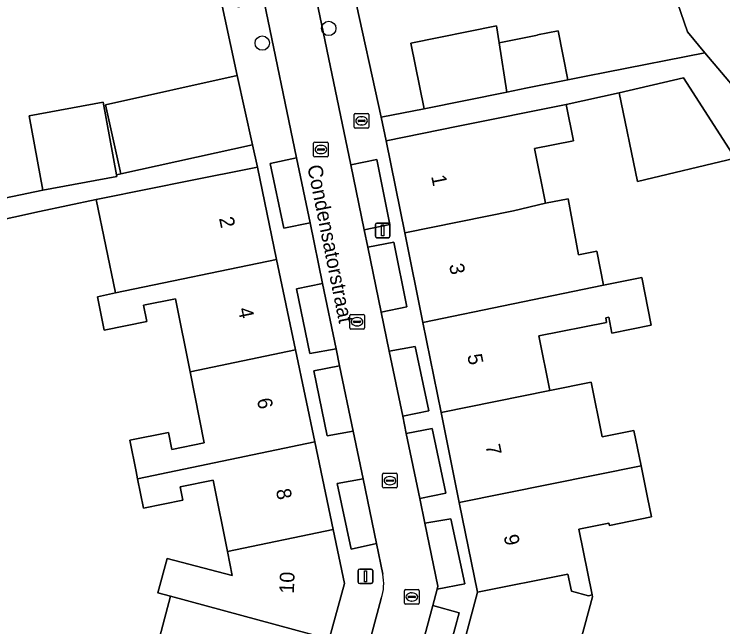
# Model space of a CAD drawing. Extents: x 162989 to 165008, y 383432 to 384338.
# Drawn here: x 163654.72 to 163703.1, y 383947.94 to 383989.79 of the extents above; entities that cross this region are included whole.
import ezdxf

# ---------------------------------------------------------------- set-up
doc = ezdxf.new("R2010")
doc.units = 0
for name, color, linetype in [('IMGEO_Boom', 7, 'Continuous'), ('IMGEO_Brandkraan', 7, 'Continuous'), ('IMGEO_Erf', 7, 'Continuous'), ('IMGEO_Kolk', 7, 'Continuous'), ('IMGEO_Lichtmast', 7, 'Continuous'), ('IMGEO_Openbare_ruimte_label', 7, 'Continuous'), ('IMGEO_Pand', 7, 'Continuous'), ('IMGEO_Pand_nummerreeks', 7, 'Continuous'), ('IMGEO_Parkeervlak_open', 7, 'Continuous'), ('IMGEO_Rijbaan_lokaal_open', 7, 'Continuous'), ('IMGEO_Rioolput', 7, 'Continuous'), ('IMGEO_Terreindeel_gesloten', 7, 'Continuous'), ('IMGEO_Voetpad_open', 7, 'Continuous')]:
    doc.layers.add(name, color=color, linetype=linetype)

msp = doc.modelspace()

# ---------------------------------------------------------------- linework, layer by layer
at = {"layer": 'IMGEO_Boom'}
for centre in [(163676.194, 383988.817), (163671.653, 383987.815)]:
    msp.add_circle(centre, 0.489, dxfattribs=at)
at = {"layer": 'IMGEO_Brandkraan'}
for p, q in [((163677.934, 383982.078), (163677.934, 383982.93)), ((163678.009, 383983.004), (163678.861, 383983.004)), ((163678.935, 383982.93), (163678.935, 383982.078)), ((163678.193, 383982.498), (163678.193, 383982.51)), ((163678.631, 383982.461), (163678.233, 383982.461)), ((163678.236, 383982.547), (163678.634, 383982.547)), ((163678.422, 383982.784), (163678.447, 383982.784)), ((163678.677, 383982.51), (163678.677, 383982.498)), ((163678.861, 383982.004), (163678.009, 383982.004)), ((163678.445, 383982.224), (163678.42, 383982.224))]:
    msp.add_line(p, q, dxfattribs=at)
for points in [[(163677.934, 383982.078), (163677.934, 383982.93)], [(163678.009, 383983.004), (163678.861, 383983.004)], [(163678.935, 383982.93), (163678.935, 383982.078)], [(163678.861, 383982.004), (163678.009, 383982.004)]]:
    msp.add_lwpolyline(points, dxfattribs=at)
for centre, radius, start, end in [((163678.011, 383982.928), 0.0765, 91.552, 178.448), ((163678.011, 383982.928), 0.0765, 91.552, 178.448), ((163678.859, 383982.928), 0.0765, 1.552, 88.448), ((163678.859, 383982.928), 0.0765, 1.552, 88.448), ((163678.233, 383982.507), 0.0403, 85.8775, 175.7526), ((163678.23, 383982.497), 0.0366, 178.938, 274.7102), ((163678.634, 383982.504), 0.043, 264.8664, 352.4533), ((163678.638, 383982.509), 0.0386, 1.7309, 96.639), ((163678.011, 383982.08), 0.0765, 181.552, 268.448), ((163678.011, 383982.08), 0.0765, 181.552, 268.448), ((163678.859, 383982.08), 0.0765, 271.552, 358.448), ((163678.859, 383982.08), 0.0765, 271.552, 358.448)]:
    msp.add_arc(centre, radius, start, end, dxfattribs=at)
for centre, major_axis, ratio, start_param, end_param in [((163678.421, 383982.504), (-0.387, 0.002), 0.722429, 4.712389, 7.853982), ((163678.446, 383982.504), (-0.39, 0.002), 0.717154, 1.570796, 4.712389)]:
    msp.add_ellipse(centre, major_axis=major_axis, ratio=ratio, start_param=start_param, end_param=end_param, dxfattribs=at)
at = {"layer": 'IMGEO_Erf'}
for points in [[(163649.338, 383976.243), (163656.674, 383977.764), (163655.732, 383982.848), (163660.79, 383983.785), (163661.71, 383978.82), (163662.003, 383978.874), (163660.958, 383983.61), (163669.94, 383985.593), (163666.955, 383999.493), (163659.023, 383997.851), (163659.53, 383995.403), (163660.627, 383995.63), (163661.134, 383993.182), (163660.787, 383993.11), (163661.265, 383990.887), (163659.452, 383990.497), (163658.97, 383992.734), (163658.895, 383993.098), (163656.322, 383992.565), (163655.913, 383994.538), (163652.306, 383993.79)], [(163664.02, 383944.869), (163665.382, 383950.025), (163664.53, 383950.25), (163665.153, 383952.612), (163669.603, 383951.438), (163669.273, 383953.081), (163668.295, 383957.948), (163666.041, 383957.495), (163666.225, 383956.579), (163663.54, 383956.04), (163663.136, 383958.052), (163663.037, 383958.543), (163662.605, 383960.691), (163665.243, 383961.221), (163665.477, 383960.058), (163667.698, 383960.504), (163666.724, 383965.353), (163665.72, 383970.349), (163663.544, 383969.912), (163663.769, 383968.792), (163660.865, 383968.209), (163660.408, 383970.486), (163661.643, 383970.744), (163660.309, 383977.13), (163656.443, 383976.322), (163631.374, 383970.769)]]:
    msp.add_lwpolyline(points, dxfattribs=at)
at = {"layer": 'IMGEO_Kolk'}
for p, q in [((163675.235, 383981.046), (163676.087, 383981.046)), ((163675.16, 383980.12), (163675.16, 383980.972)), ((163675.419, 383980.54), (163675.419, 383980.552)), ((163675.857, 383980.503), (163675.459, 383980.503)), ((163675.462, 383980.589), (163675.86, 383980.589)), ((163675.648, 383980.826), (163675.673, 383980.826)), ((163675.903, 383980.552), (163675.903, 383980.54)), ((163676.161, 383980.972), (163676.161, 383980.12)), ((163676.087, 383980.046), (163675.235, 383980.046)), ((163675.671, 383980.266), (163675.646, 383980.266)), ((163677.627, 383968.354), (163677.627, 383969.206)), ((163677.702, 383969.28), (163678.554, 383969.28)), ((163678.115, 383969.06), (163678.14, 383969.06)), ((163678.628, 383969.206), (163678.628, 383968.354)), ((163677.886, 383968.774), (163677.886, 383968.786)), ((163678.324, 383968.737), (163677.926, 383968.737)), ((163677.929, 383968.823), (163678.327, 383968.823)), ((163678.138, 383968.5), (163678.113, 383968.5)), ((163678.37, 383968.786), (163678.37, 383968.774)), ((163678.554, 383968.28), (163677.702, 383968.28)), ((163679.873, 383957.498), (163679.873, 383958.35)), ((163679.948, 383958.424), (163680.8, 383958.424)), ((163680.874, 383958.35), (163680.874, 383957.498)), ((163680.132, 383957.918), (163680.132, 383957.93)), ((163680.57, 383957.881), (163680.172, 383957.881)), ((163680.175, 383957.967), (163680.573, 383957.967)), ((163680.361, 383958.204), (163680.386, 383958.204)), ((163680.616, 383957.93), (163680.616, 383957.918)), ((163680.8, 383957.424), (163679.948, 383957.424)), ((163680.384, 383957.644), (163680.359, 383957.644))]:
    msp.add_line(p, q, dxfattribs=at)
for points in [[(163675.235, 383981.046), (163676.087, 383981.046)], [(163675.16, 383980.12), (163675.16, 383980.972)], [(163676.161, 383980.972), (163676.161, 383980.12)], [(163676.087, 383980.046), (163675.235, 383980.046)], [(163677.627, 383968.354), (163677.627, 383969.206)], [(163677.702, 383969.28), (163678.554, 383969.28)], [(163678.628, 383969.206), (163678.628, 383968.354)], [(163678.554, 383968.28), (163677.702, 383968.28)], [(163679.873, 383957.498), (163679.873, 383958.35)], [(163679.948, 383958.424), (163680.8, 383958.424)], [(163680.874, 383958.35), (163680.874, 383957.498)], [(163680.8, 383957.424), (163679.948, 383957.424)]]:
    msp.add_lwpolyline(points, dxfattribs=at)
for centre, radius, start, end in [((163675.237, 383980.97), 0.0765, 91.552, 178.448), ((163675.237, 383980.97), 0.0765, 91.552, 178.448), ((163676.085, 383980.97), 0.0765, 1.552, 88.448), ((163676.085, 383980.97), 0.0765, 1.552, 88.448), ((163675.459, 383980.549), 0.0403, 85.8775, 175.7526), ((163675.456, 383980.539), 0.0366, 178.938, 274.7102), ((163675.86, 383980.546), 0.043, 264.8664, 352.4533), ((163675.864, 383980.551), 0.0386, 1.7309, 96.639), ((163675.237, 383980.122), 0.0765, 181.552, 268.448), ((163675.237, 383980.122), 0.0765, 181.552, 268.448), ((163676.085, 383980.122), 0.0765, 271.552, 358.448), ((163676.085, 383980.122), 0.0765, 271.552, 358.448), ((163677.704, 383969.204), 0.0765, 91.552, 178.448), ((163677.704, 383969.204), 0.0765, 91.552, 178.448), ((163678.552, 383969.204), 0.0765, 1.552, 88.448), ((163678.552, 383969.204), 0.0765, 1.552, 88.448), ((163677.926, 383968.783), 0.0403, 85.8775, 175.7526), ((163677.923, 383968.773), 0.0366, 178.938, 274.7102), ((163678.327, 383968.78), 0.043, 264.8664, 352.4533), ((163678.331, 383968.785), 0.0386, 1.7309, 96.639), ((163677.704, 383968.356), 0.0765, 181.552, 268.448), ((163677.704, 383968.356), 0.0765, 181.552, 268.448), ((163678.552, 383968.356), 0.0765, 271.552, 358.448), ((163678.552, 383968.356), 0.0765, 271.552, 358.448), ((163679.95, 383958.348), 0.0765, 91.552, 178.448), ((163679.95, 383958.348), 0.0765, 91.552, 178.448), ((163680.798, 383958.348), 0.0765, 1.552, 88.448), ((163680.798, 383958.348), 0.0765, 1.552, 88.448), ((163680.172, 383957.927), 0.0403, 85.8775, 175.7526), ((163680.169, 383957.917), 0.0366, 178.938, 274.7102), ((163680.573, 383957.924), 0.043, 264.8664, 352.4533), ((163680.577, 383957.929), 0.0386, 1.7309, 96.639), ((163679.95, 383957.5), 0.0765, 181.552, 268.448), ((163679.95, 383957.5), 0.0765, 181.552, 268.448), ((163680.798, 383957.5), 0.0765, 271.552, 358.448), ((163680.798, 383957.5), 0.0765, 271.552, 358.448)]:
    msp.add_arc(centre, radius, start, end, dxfattribs=at)
for centre, major_axis, ratio, start_param, end_param in [((163675.647, 383980.546), (-0.387, 0.002), 0.722429, 4.712389, 7.853982), ((163675.672, 383980.546), (-0.39, 0.002), 0.717154, 1.570796, 4.712389), ((163678.114, 383968.78), (-0.387, 0.002), 0.722429, 4.712389, 7.853982), ((163678.139, 383968.78), (-0.39, 0.002), 0.717154, 1.570796, 4.712389), ((163680.36, 383957.924), (-0.387, 0.002), 0.722429, 4.712389, 7.853982), ((163680.385, 383957.924), (-0.39, 0.002), 0.717154, 1.570796, 4.712389)]:
    msp.add_ellipse(centre, major_axis=major_axis, ratio=ratio, start_param=start_param, end_param=end_param, dxfattribs=at)
at = {"layer": 'IMGEO_Lichtmast'}
for p, q in [((163679.378, 383974.623), (163679.378, 383975.423)), ((163679.378, 383975.423), (163679.378, 383974.623)), ((163679.478, 383975.523), (163680.268, 383975.523)), ((163680.268, 383975.523), (163679.478, 383975.523)), ((163680.368, 383975.423), (163680.368, 383974.623)), ((163680.368, 383974.623), (163680.368, 383975.423)), ((163680.268, 383974.523), (163679.478, 383974.523)), ((163679.478, 383974.523), (163680.268, 383974.523)), ((163678.208, 383950.987), (163678.208, 383951.787)), ((163678.208, 383951.787), (163678.208, 383950.987)), ((163678.308, 383951.887), (163679.098, 383951.887)), ((163679.098, 383951.887), (163678.308, 383951.887)), ((163679.198, 383951.787), (163679.198, 383950.987)), ((163679.198, 383950.987), (163679.198, 383951.787)), ((163679.098, 383950.887), (163678.308, 383950.887)), ((163678.308, 383950.887), (163679.098, 383950.887))]:
    msp.add_line(p, q, dxfattribs=at)
for points in [[(163679.798, 383975.398), (163679.948, 383975.398), (163679.948, 383974.648), (163679.798, 383974.648), (163679.798, 383975.398)], [(163678.628, 383951.762), (163678.778, 383951.762), (163678.778, 383951.012), (163678.628, 383951.012), (163678.628, 383951.762)]]:
    msp.add_lwpolyline(points, dxfattribs=at)
for centre, start, end in [((163679.478, 383975.423), 90, 180), ((163679.478, 383975.423), 90, 180), ((163680.268, 383975.423), 0, 90), ((163680.268, 383975.423), 360, 90), ((163679.478, 383974.623), 180, 270), ((163679.478, 383974.623), 180, 270), ((163680.268, 383974.623), 270, 0), ((163680.268, 383974.623), 270, 0), ((163678.308, 383951.787), 90, 180), ((163678.308, 383951.787), 90, 180), ((163679.098, 383951.787), 0, 90), ((163679.098, 383951.787), 360, 90), ((163678.308, 383950.987), 180, 270), ((163678.308, 383950.987), 180, 270), ((163679.098, 383950.987), 270, 0), ((163679.098, 383950.987), 270, 0)]:
    msp.add_arc(centre, 0.1, start, end, dxfattribs=at)
at = {"layer": 'IMGEO_Pand'}
for points in [[(163703.909, 383997.461), (163701.43, 383997.012), (163699.309, 383996.628), (163698.002, 383996.392), (163700.685, 383988.577), (163701.884, 383987.16), (163725.748, 383958.959), (163732.007, 383964.256)], [(163687.821, 383987.842), (163687.64, 383988.996), (163681.808, 383987.821), (163682.712, 383983.332), (163688.349, 383984.467)], [(163687.821, 383987.842), (163688.349, 383984.467), (163689.65, 383984.729), (163692.528, 383985.309), (163691.855, 383988.652), (163690.459, 383988.371), (163690.442, 383988.369)], [(163669.94, 383985.593), (163660.958, 383983.61), (163662.003, 383978.874), (163670.986, 383980.857)], [(163696.019, 383984.426), (163697.272, 383978.372), (163703.944, 383979.959), (163700.411, 383985.439)], [(163660.79, 383983.785), (163655.732, 383982.848), (163656.674, 383977.764), (163661.732, 383978.702), (163661.71, 383978.82)], [(163681.392, 383974.86), (163688.818, 383976.356), (163690.996, 383976.883), (163690.244, 383980.612), (163692.91, 383981.149), (163692.412, 383983.618), (163685.027, 383982.137), (163680.125, 383981.149)], [(163671.32, 383979.343), (163666.419, 383978.358), (163664.156, 383977.903), (163660.309, 383977.13), (163661.643, 383970.744), (163672.636, 383973.04)], [(163694.494, 383973.612), (163693.255, 383973.362), (163692.532, 383977.174), (163690.996, 383976.883), (163688.818, 383976.356), (163681.392, 383974.86), (163682.629, 383968.718), (163694.965, 383971.271)], [(163672.636, 383973.04), (163661.643, 383970.744), (163660.408, 383970.486), (163660.865, 383968.209), (163663.769, 383968.792), (163663.544, 383969.912), (163665.72, 383970.349), (163666.724, 383965.353), (163673.928, 383966.857)], [(163690.543, 383967.808), (163695.164, 383968.738), (163695.103, 383969.043), (163695.314, 383969.086), (163695.534, 383967.995), (163698.218, 383968.536), (163697.562, 383971.794), (163694.965, 383971.271), (163682.629, 383968.718), (163683.866, 383962.577), (163691.295, 383964.077)], [(163666.724, 383965.353), (163667.698, 383960.504), (163665.477, 383960.058), (163665.243, 383961.221), (163662.605, 383960.691), (163663.037, 383958.543), (163663.136, 383958.052), (163675.239, 383960.58), (163673.928, 383966.857)], [(163697.52, 383958.936), (163697.033, 383961.354), (163694.86, 383960.917), (163694.108, 383964.649), (163691.295, 383964.077), (163683.866, 383962.577), (163685.103, 383956.435)], [(163663.136, 383958.052), (163663.54, 383956.04), (163666.225, 383956.579), (163666.041, 383957.495), (163668.295, 383957.948), (163669.273, 383953.081), (163676.49, 383954.588), (163675.239, 383960.58)], [(163693.271, 383954.603), (163695.326, 383955.017), (163695.357, 383954.864), (163698.224, 383955.442), (163697.957, 383956.769), (163697.52, 383958.936), (163685.103, 383956.435), (163686.34, 383950.294), (163692.525, 383951.539), (163692.761, 383950.365), (163693.934, 383950.051), (163694.173, 383950.124)], [(163676.49, 383954.588), (163669.273, 383953.081), (163669.603, 383951.438), (163665.153, 383952.612), (163664.53, 383950.25), (163665.382, 383950.025), (163676.227, 383947.087), (163677.26, 383950.901)], [(163694.199, 383949.993), (163694.173, 383950.124), (163693.934, 383950.051), (163692.761, 383950.365), (163692.525, 383951.539), (163686.34, 383950.294), (163684.751, 383944.336), (163696.922, 383941.077), (163700.854, 383940.736), (163702.069, 383945.343), (163697.97, 383946.428), (163697.154, 383943.476), (163694.808, 383944.104), (163694.612, 383943.373), (163692.573, 383943.919)], [(163676.227, 383947.087), (163665.382, 383950.025), (163664.02, 383944.869), (163663.682, 383943.589), (163667.222, 383942.653), (163667.294, 383942.927), (163674.567, 383940.957)]]:
    msp.add_lwpolyline(points, close=True, dxfattribs=at)
at = {"layer": 'IMGEO_Parkeervlak_open'}
for points in [[(163673.995, 383979.982), (163672.196, 383979.597), (163673.129, 383975.176), (163674.916, 383975.532)], [(163677.694, 383979.491), (163678.612, 383975.053), (163680.366, 383975.43), (163679.474, 383979.854)], [(163678.855, 383973.878), (163679.775, 383969.429), (163681.526, 383969.806), (163680.633, 383974.215)], [(163675.773, 383971.383), (163673.988, 383971.033), (163674.904, 383966.6), (163676.693, 383966.931)], [(163681.243, 383962.33), (163683.02, 383962.686), (163682.102, 383967.099), (163680.324, 383966.774)], [(163676.938, 383965.761), (163675.169, 383965.423), (163676.086, 383960.979), (163677.855, 383961.311)], [(163681.49, 383961.136), (163682.406, 383956.709), (163684.188, 383957.065), (163683.248, 383961.496)], [(163679.446, 383953.639), (163678.534, 383958.049), (163676.761, 383957.728), (163677.719, 383953.253)], [(163682.756, 383955.016), (163683.646, 383950.713), (163683.589, 383950.502), (163685.479, 383950.868), (163684.531, 383955.321)], [(163683.292, 383949.391), (163682.115, 383945.004), (163683.91, 383944.523), (163685.107, 383948.901)]]:
    msp.add_lwpolyline(points, close=True, dxfattribs=at)
at = {"layer": 'IMGEO_Rijbaan_lokaal_open'}
for points in [[(163682.756, 383955.016), (163682.406, 383956.709), (163681.49, 383961.136), (163681.243, 383962.33), (163680.324, 383966.774), (163679.775, 383969.429), (163678.855, 383973.878), (163678.612, 383975.053), (163677.694, 383979.491), (163675.245, 383991.331), (163674.326, 383995.772), (163673.959, 383997.551), (163673.452, 384000), (163673.037, 384002.004), (163671.293, 384010.439)], [(163667.83, 384009.769), (163669.585, 384001.291), (163669.852, 384000), (163670.508, 383996.831), (163670.871, 383995.074), (163671.79, 383990.634), (163673.995, 383979.982), (163674.916, 383975.532), (163675.773, 383971.383), (163676.693, 383966.931), (163676.938, 383965.761), (163677.855, 383961.311), (163678.534, 383958.049), (163679.446, 383953.639), (163679.88, 383951.543)], [(163679.785, 383949.861), (163678.54, 383945.274), (163677.344, 383940.871), (163677.03, 383939.713), (163675.846, 383935.353), (163675.124, 383932.682), (163673.947, 383928.341), (163672.545, 383923.205), (163678.094, 383921.638), (163678.667, 383923.699), (163676.598, 383924.257), (163677.363, 383927.171), (163678.514, 383931.573), (163678.824, 383932.729), (163680.003, 383937.128), (163680.465, 383938.851), (163681.64, 383943.23), (163682.115, 383945.004), (163683.292, 383949.391), (163683.589, 383950.502), (163683.646, 383950.713), (163682.756, 383955.016)]]:
    msp.add_lwpolyline(points, dxfattribs=at)
msp.add_arc((163676.657, 383950.881), 3.29, 341.9321, 11.6026, dxfattribs=at)
at = {"layer": 'IMGEO_Rioolput'}
for p, q in [((163681.367, 383949.552), (163681.367, 383950.404)), ((163681.442, 383950.478), (163682.294, 383950.478)), ((163681.669, 383950.021), (163682.067, 383950.021)), ((163681.855, 383950.258), (163681.88, 383950.258)), ((163682.368, 383950.404), (163682.368, 383949.552)), ((163681.626, 383949.972), (163681.626, 383949.984)), ((163682.064, 383949.935), (163681.666, 383949.935)), ((163681.878, 383949.698), (163681.853, 383949.698)), ((163682.11, 383949.984), (163682.11, 383949.972)), ((163682.294, 383949.478), (163681.442, 383949.478))]:
    msp.add_line(p, q, dxfattribs=at)
for points in [[(163681.367, 383949.552), (163681.367, 383950.404)], [(163681.442, 383950.478), (163682.294, 383950.478)], [(163682.368, 383950.404), (163682.368, 383949.552)], [(163682.294, 383949.478), (163681.442, 383949.478)]]:
    msp.add_lwpolyline(points, dxfattribs=at)
for centre, radius, start, end in [((163681.444, 383950.402), 0.0765, 91.552, 178.448), ((163681.444, 383950.402), 0.0765, 91.552, 178.448), ((163681.666, 383949.981), 0.0403, 85.8775, 175.7526), ((163682.071, 383949.983), 0.0386, 1.7309, 96.639), ((163682.292, 383950.402), 0.0765, 1.552, 88.448), ((163682.292, 383950.402), 0.0765, 1.552, 88.448), ((163681.444, 383949.554), 0.0765, 181.552, 268.448), ((163681.444, 383949.554), 0.0765, 181.552, 268.448), ((163681.663, 383949.971), 0.0366, 178.938, 274.7102), ((163682.067, 383949.978), 0.043, 264.8664, 352.4533), ((163682.292, 383949.554), 0.0765, 271.552, 358.448), ((163682.292, 383949.554), 0.0765, 271.552, 358.448)]:
    msp.add_arc(centre, radius, start, end, dxfattribs=at)
for centre, major_axis, ratio, start_param, end_param in [((163681.854, 383949.978), (-0.387, 0.002), 0.722429, 4.712389, 7.853982), ((163681.879, 383949.978), (-0.39, 0.002), 0.717154, 1.570796, 4.712389)]:
    msp.add_ellipse(centre, major_axis=major_axis, ratio=ratio, start_param=start_param, end_param=end_param, dxfattribs=at)
at = {"layer": 'IMGEO_Terreindeel_gesloten'}
for points in [[(163675.998, 384000), (163679.774, 383982.752), (163682.712, 383983.332), (163681.808, 383987.821), (163687.64, 383988.996), (163687.821, 383987.842), (163690.442, 383988.369), (163690.459, 383988.371), (163691.855, 383988.652), (163692.528, 383985.309), (163693.775, 383985.56), (163695.163, 383985.839), (163701.884, 383987.16), (163700.685, 383988.577), (163698.002, 383996.392)], [(163703.944, 383979.959), (163697.272, 383978.372), (163696.019, 383984.426), (163692.412, 383983.618), (163692.91, 383981.149), (163690.244, 383980.612), (163690.996, 383976.883), (163692.532, 383977.174), (163693.255, 383973.362), (163694.494, 383973.612), (163694.965, 383971.271), (163697.562, 383971.794), (163698.218, 383968.536), (163695.534, 383967.995), (163695.314, 383969.086), (163695.103, 383969.043), (163695.164, 383968.738), (163690.543, 383967.808), (163691.295, 383964.077), (163694.108, 383964.649), (163694.86, 383960.917), (163697.033, 383961.354), (163697.52, 383958.936), (163697.957, 383956.769), (163698.224, 383955.442), (163695.357, 383954.864), (163695.326, 383955.017), (163693.271, 383954.603), (163694.173, 383950.124), (163694.199, 383949.993), (163692.573, 383943.919)]]:
    msp.add_lwpolyline(points, dxfattribs=at)
at = {"layer": 'IMGEO_Voetpad_open'}
for points in [[(163671.79, 383990.634), (163670.02, 383990.28), (163669.11, 383994.717), (163670.871, 383995.074), (163670.508, 383996.831), (163668.746, 383996.489), (163668.003, 384000), (163667.806, 384000.931), (163669.585, 384001.291), (163667.83, 384009.769), (163664.838, 384009.691), (163665.922, 384004.457), (163666.955, 383999.493), (163669.94, 383985.593), (163670.986, 383980.857), (163671.32, 383979.343), (163672.636, 383973.04), (163673.928, 383966.857), (163675.239, 383960.58), (163676.49, 383954.588), (163677.26, 383950.901), (163676.227, 383947.087)], [(163684.751, 383944.336), (163686.34, 383950.294), (163685.103, 383956.435), (163683.866, 383962.577), (163682.629, 383968.718), (163681.392, 383974.86), (163680.125, 383981.149), (163679.774, 383982.752), (163675.998, 384000)], [(163675.245, 383991.331), (163677.694, 383979.491), (163679.474, 383979.854), (163680.366, 383975.43), (163678.612, 383975.053), (163678.855, 383973.878), (163680.633, 383974.215), (163681.526, 383969.806), (163679.775, 383969.429), (163680.324, 383966.774), (163682.102, 383967.099), (163683.02, 383962.686), (163681.243, 383962.33), (163681.49, 383961.136), (163683.248, 383961.496), (163684.188, 383957.065), (163682.406, 383956.709), (163682.756, 383955.016), (163684.531, 383955.321), (163685.479, 383950.868), (163683.589, 383950.502), (163683.292, 383949.391), (163685.107, 383948.901), (163683.91, 383944.523)], [(163679.88, 383951.543), (163679.446, 383953.639), (163677.719, 383953.253), (163676.761, 383957.728), (163678.534, 383958.049), (163677.855, 383961.311), (163676.086, 383960.979), (163675.169, 383965.423), (163676.938, 383965.761), (163676.693, 383966.931), (163674.904, 383966.6), (163673.988, 383971.033), (163675.773, 383971.383), (163674.916, 383975.532), (163673.129, 383975.176), (163672.196, 383979.597), (163673.995, 383979.982), (163671.79, 383990.634)], [(163725.748, 383958.959), (163701.884, 383987.16), (163695.163, 383985.839), (163693.775, 383985.56), (163692.528, 383985.309), (163689.65, 383984.729), (163688.349, 383984.467), (163682.712, 383983.332), (163679.774, 383982.752), (163680.125, 383981.149), (163685.027, 383982.137), (163692.412, 383983.618), (163696.019, 383984.426), (163700.411, 383985.439), (163703.944, 383979.959)], [(163631.374, 383970.769), (163656.443, 383976.322), (163660.309, 383977.13), (163664.156, 383977.903), (163666.419, 383978.358), (163671.32, 383979.343), (163670.986, 383980.857), (163662.003, 383978.874), (163661.71, 383978.82), (163661.732, 383978.702), (163656.674, 383977.764), (163649.338, 383976.243)], [(163678.54, 383945.274), (163679.785, 383949.861)]]:
    msp.add_lwpolyline(points, dxfattribs=at)
msp.add_arc((163676.657, 383950.881), 3.29, 341.9321, 11.6026, dxfattribs=at)

# ---------------------------------------------------------------- texts
at = {"layer": 'IMGEO_Openbare_ruimte_label'}
msp.add_text('Condensatorstraat', height=1, rotation=281.4223, dxfattribs=at).set_placement((163674.725, 383979.403))
at = {"layer": 'IMGEO_Pand_nummerreeks'}
for s, rotation, p in [('1', 281.3885, (163683.184, 383978.719)), ('2', 281.797, (163668.698, 383975.85)), ('3', 281.3902, (163684.405, 383972.66)), ('4', 281.797, (163669.991, 383969.659)), ('5', 281.3902, (163685.648, 383966.489)), ('6', 281.7964, (163671.284, 383963.47)), ('7', 281.3885, (163686.891, 383960.318)), ('8', 281.7964, (163672.578, 383957.278)), ('9', 281.3902, (163688.134, 383954.147)), ('10', 87.9929, (163673.814, 383950.194))]:
    msp.add_text(s, height=1, rotation=rotation, dxfattribs=at).set_placement(p)

doc.saveas('drawing.dxf')
